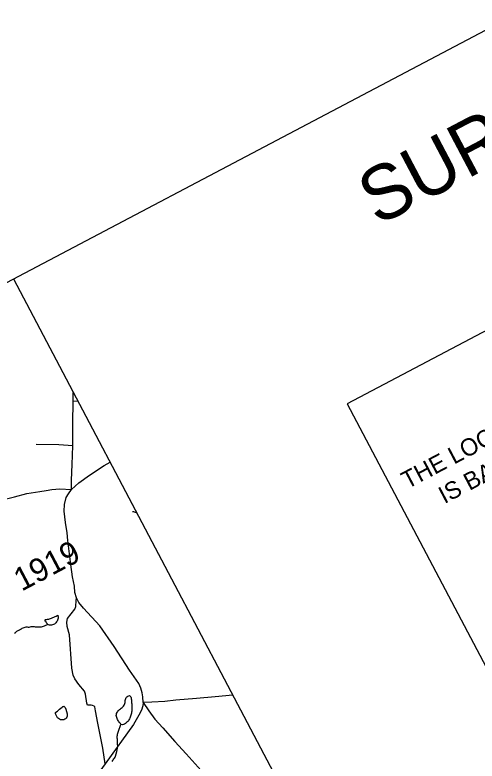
# Model space of a CAD drawing. Extents: x 1379448 to 1382868, y 593769 to 596827.
# Drawn here: x 1380162.2 to 1380457.9, y 595600.1 to 596077.5 of the extents above; entities that cross this region are included whole.
import ezdxf

# ---------------------------------------------------------------- set-up
doc = ezdxf.new("R2010")
doc.units = 0
for name, color, linetype in [('CTL Sheet Border CELL', 7, 'Continuous'), ('CTL Sheet Datum Description CELL', 7, 'Continuous'), ('Old_Level_1', 7, 'Continuous'), ('Old_Level_32', 7, 'Continuous'), ('Old_Level_35', 7, 'Continuous'), ('Old_Level_62', 7, 'Continuous'), ('Old_Level_8', 7, 'Continuous')]:
    doc.layers.add(name, color=color, linetype=linetype)

msp = doc.modelspace()

# ---------------------------------------------------------------- linework, layer by layer
at = {"layer": 'CTL Sheet Border CELL'}
msp.add_lwpolyline([(1381803.77, 596774.44), (1379496.12, 595557.87), (1380347.71, 593942.52), (1382655.37, 595159.09)], close=True, dxfattribs=at)
at = {"layer": 'CTL Sheet Datum Description CELL'}
msp.add_lwpolyline([(1380532.47, 595529.6), (1380967.69, 595759.04), (1380810.07, 596058.04), (1380374.84, 595828.59)], close=True, dxfattribs=at)
at = {"layer": 'Old_Level_1'}
msp.add_line((1380161.32, 595908.56), (1380447.79, 595365.17), dxfattribs=at)
at = {"layer": 'Old_Level_32'}
for points in [[(1380199.6, 595830.38), (1380199.58, 595835.98)], [(1380198.39, 595773.84), (1380198.46, 595779.9), (1380198.76, 595789.83), (1380199.28, 595801.81), (1380199.23, 595816.16), (1380199.6, 595830.38)], [(1380199.6, 595830.38), (1380202.48, 595830.48)], [(1380198.39, 595773.84), (1380200.73, 595776.02), (1380203.2, 595778.1), (1380210, 595782.93), (1380219.3, 595789.2), (1380223.15, 595791.27)], [(1380153.3, 595766.99), (1380162.08, 595769.07), (1380169.78, 595771.37), (1380178.26, 595772.53), (1380182.28, 595773.17), (1380185.83, 595773.88), (1380190.88, 595774.22), (1380198.39, 595773.84)], [(1380244.23, 595637.58), (1380244.17, 595641.28), (1380243.6, 595643.84), (1380242.77, 595646.67), (1380241.54, 595649.71), (1380235.62, 595658.29), (1380225.71, 595673.49), (1380216.48, 595686.7), (1380206.11, 595697.83), (1380203.17, 595701.46), (1380201.65, 595704.63), (1380200.56, 595707.96), (1380200.38, 595712.05), (1380199.02, 595718.07), (1380198.09, 595725.8), (1380196.11, 595741.28), (1380195.7, 595746.14), (1380194.58, 595752.64), (1380193.68, 595759.97), (1380193.93, 595764.3), (1380194.92, 595768.63), (1380196.43, 595771.1), (1380198.39, 595773.84)], [(1380301.66, 595642.36), (1380290.25, 595641.1), (1380278.46, 595640.19), (1380265.1, 595639.04), (1380258.19, 595638.21), (1380249.8, 595637.73), (1380244.23, 595637.58)], [(1380244.23, 595637.58), (1380244.1, 595635.42), (1380243.16, 595632.69), (1380241.51, 595629.37), (1380238.04, 595623.43), (1380220.02, 595598.4), (1380210.75, 595585.79), (1380208.21, 595581.85), (1380203.06, 595572.07), (1380198, 595560.29), (1380197.14, 595556.31), (1380196.92, 595554.25)], [(1380244.23, 595637.58), (1380247.99, 595632.28), (1380251.75, 595626.93), (1380256.95, 595621.37), (1380264.47, 595612.57), (1380271.7, 595604.76), (1380279.55, 595596.24), (1380285.26, 595589.71), (1380289.8, 595585.12), (1380296.28, 595578.6), (1380304.69, 595569.99), (1380314.57, 595556.83)]]:
    msp.add_lwpolyline(points, dxfattribs=at)
at = {"layer": 'Old_Level_35'}
for points in [[(1380199.28, 595801.81), (1380190.28, 595802.45), (1380175.87, 595802.69)], [(1380220.02, 595598.4), (1380218.46, 595608.26), (1380215.23, 595624.36), (1380213.83, 595632.16), (1380213.26, 595634.74), (1380212.97, 595635.13), (1380211.86, 595635.74), (1380211.01, 595635.85), (1380209.07, 595635.77), (1380208.71, 595635.95), (1380208.25, 595637.24), (1380207.49, 595642.86), (1380206.84, 595644.86), (1380203.16, 595649.01), (1380200.65, 595652.76), (1380199.53, 595655.16), (1380198.68, 595659.56), (1380197.08, 595680.96), (1380195.72, 595686.19), (1380195.36, 595689.05), (1380195.97, 595691.28), (1380200.57, 595697.25), (1380201.27, 595698.97), (1380201.4, 595702.91), (1380201.65, 595704.63)]]:
    msp.add_lwpolyline(points, dxfattribs=at)
at = {"layer": 'Old_Level_62'}
msp.add_line((1380229.62, 595622.29), (1380230.02, 595623.43), dxfattribs=at)
for points in [[(1380240.18, 595758.98), (1380240.12, 595758.99), (1380239.48, 595759.13), (1380238.84, 595759.31), (1380238.22, 595759.5), (1380237.41, 595759.54)], [(1380183.14, 595687.44), (1380182.86, 595688.03), (1380182.54, 595688.6), (1380182.14, 595689.13), (1380181.74, 595689.65), (1380181.47, 595690.23), (1380181.87, 595690.69), (1380182.52, 595690.77), (1380183.18, 595690.81), (1380183.84, 595690.89), (1380184.45, 595691.09), (1380185.68, 595691.54), (1380188.06, 595692.54), (1380188.64, 595692.85), (1380189.8, 595693.51), (1380189.95, 595692.21), (1380189.83, 595691.57), (1380189.46, 595690.3), (1380189.19, 595689.71), (1380188.84, 595689.15), (1380188.45, 595688.62), (1380188.02, 595688.13), (1380187.47, 595687.76), (1380186.89, 595687.44), (1380186.28, 595687.2), (1380185.63, 595687.09), (1380184.97, 595687.05), (1380184.32, 595687.1), (1380183.14, 595687.44)], [(1380162.02, 595681.88), (1380162.53, 595682.31), (1380163.03, 595682.73), (1380163.56, 595683.12), (1380165.23, 595684.13), (1380165.8, 595684.44), (1380166.39, 595684.74), (1380166.98, 595685.03), (1380167.58, 595685.31), (1380168.18, 595685.56), (1380168.81, 595685.77), (1380169.45, 595685.9), (1380170.11, 595685.94), (1380170.76, 595685.87), (1380171.39, 595685.71), (1380172.02, 595685.88), (1380172.66, 595686.09), (1380173.29, 595686.24), (1380173.94, 595686.26), (1380174.59, 595686.18), (1380175.24, 595686.06), (1380175.89, 595685.94), (1380176.55, 595685.89), (1380177.2, 595685.89), (1380177.86, 595685.93), (1380178.52, 595685.99), (1380179.17, 595686.07), (1380179.81, 595686.19), (1380180.45, 595686.35), (1380181.07, 595686.55), (1380181.68, 595686.79), (1380183.14, 595687.44)], [(1380230.02, 595623.43), (1380229.83, 595624.07), (1380229.4, 595624.55), (1380228.95, 595625.03), (1380228.58, 595625.57), (1380228.25, 595626.14), (1380227.94, 595626.72), (1380227.64, 595627.31), (1380227.37, 595627.9), (1380227.15, 595628.52), (1380227.09, 595629.18), (1380227.13, 595629.83), (1380227.31, 595630.47), (1380227.57, 595631.07), (1380227.87, 595631.65), (1380228.26, 595632.18), (1380228.72, 595632.65), (1380229.22, 595633.07), (1380229.75, 595633.47), (1380230.27, 595633.87), (1380230.79, 595634.28), (1380231.26, 595634.72), (1380231.68, 595635.23), (1380232.04, 595635.79), (1380232.35, 595636.37), (1380232.56, 595636.99), (1380232.69, 595637.63), (1380232.78, 595638.29), (1380232.86, 595638.95), (1380232.97, 595639.59), (1380233.14, 595640.22), (1380233.47, 595640.8), (1380233.91, 595641.28), (1380234.46, 595641.63), (1380235.49, 595642.14), (1380235.98, 595641.69), (1380236.36, 595641.17), (1380236.57, 595640.55), (1380236.7, 595639.89), (1380236.77, 595639.24), (1380236.8, 595638.58), (1380236.82, 595637.92), (1380236.86, 595637.27), (1380237.03, 595636.65), (1380237.06, 595636), (1380237.07, 595635.34), (1380237.06, 595634.68), (1380237.04, 595634.02), (1380237.02, 595633.37), (1380236.99, 595632.71), (1380236.93, 595632.05), (1380236.86, 595631.4), (1380236.76, 595630.76), (1380236.63, 595630.11), (1380236.48, 595629.47), (1380236.28, 595628.84), (1380236.05, 595628.23), (1380235.79, 595627.63), (1380235.49, 595627.03), (1380235.17, 595626.46), (1380234.82, 595625.92), (1380234.39, 595625.41), (1380233.93, 595624.95), (1380233.45, 595624.5), (1380232.91, 595624.11), (1380232.35, 595623.76), (1380231.75, 595623.47), (1380231.12, 595623.38), (1380230.02, 595623.43)], [(1380188.47, 595631.35), (1380189.41, 595632.12), (1380190.83, 595633.21), (1380192.37, 595634.49), (1380192.92, 595634.91), (1380193.24, 595635.09), (1380193.57, 595635.14), (1380193.81, 595635.06), (1380194.06, 595634.82), (1380194.34, 595634.33), (1380194.81, 595633.27), (1380195.25, 595631.81), (1380195.63, 595630.33), (1380195.74, 595629.47), (1380195.63, 595628.78), (1380195.47, 595628.13), (1380195.08, 595627.57), (1380194.57, 595627.12), (1380194.07, 595626.81), (1380193.5, 595626.55), (1380192.77, 595626.4), (1380191.98, 595626.42), (1380191.31, 595626.55), (1380190.75, 595626.86), (1380190.09, 595627.31), (1380189.58, 595627.84), (1380189.01, 595628.7), (1380188.37, 595630), (1380188.15, 595630.61), (1380188.15, 595630.96), (1380188.25, 595631.17), (1380188.47, 595631.35)], [(1380224.49, 595599.8), (1380224.79, 595600.39), (1380225.1, 595600.96), (1380225.5, 595601.49), (1380225.93, 595602.01), (1380226.29, 595602.55), (1380226.53, 595603.15), (1380227.49, 595606.26), (1380228.05, 595609.48), (1380228.03, 595610.12), (1380227.94, 595610.78), (1380227.87, 595611.43), (1380227.84, 595612.09), (1380227.81, 595612.74), (1380227.78, 595613.4), (1380227.77, 595614.06), (1380227.75, 595614.71), (1380227.75, 595615.37), (1380227.74, 595616.02), (1380227.77, 595616.68), (1380227.9, 595617.32), (1380228.1, 595617.95), (1380228.31, 595618.57), (1380228.52, 595619.19), (1380228.74, 595619.81), (1380228.96, 595620.43), (1380229.18, 595621.05), (1380229.4, 595621.67), (1380229.62, 595622.29)]]:
    msp.add_lwpolyline(points, dxfattribs=at)

# ---------------------------------------------------------------- texts
at = {"layer": 'CTL Sheet Border CELL'}
msp.add_text('SURVEY CONTROL SHEET', height=34.7826, rotation=27.7977, dxfattribs=at).set_placement((1380394.2, 595942.13))
at = {"layer": 'CTL Sheet Datum Description CELL'}
for s, p in [('THE LOCALIZED COORDINATE SYSTEM DEVELOPED FOR THIS PROJECT', (1380413.25, 595773.96)), ('IS BASED ON THE STATE PLANE COORDINATES ESTABLISHED BY', (1380436.97, 595764.44))]:
    msp.add_text(s, height=11.07, rotation=27.7977, dxfattribs=at).set_placement(p)
at = {"layer": 'Old_Level_8'}
msp.add_text('1919', height=14.764, rotation=27.7977, dxfattribs=at).set_placement((1380166.53, 595708.44))

doc.saveas('drawing.dxf')
